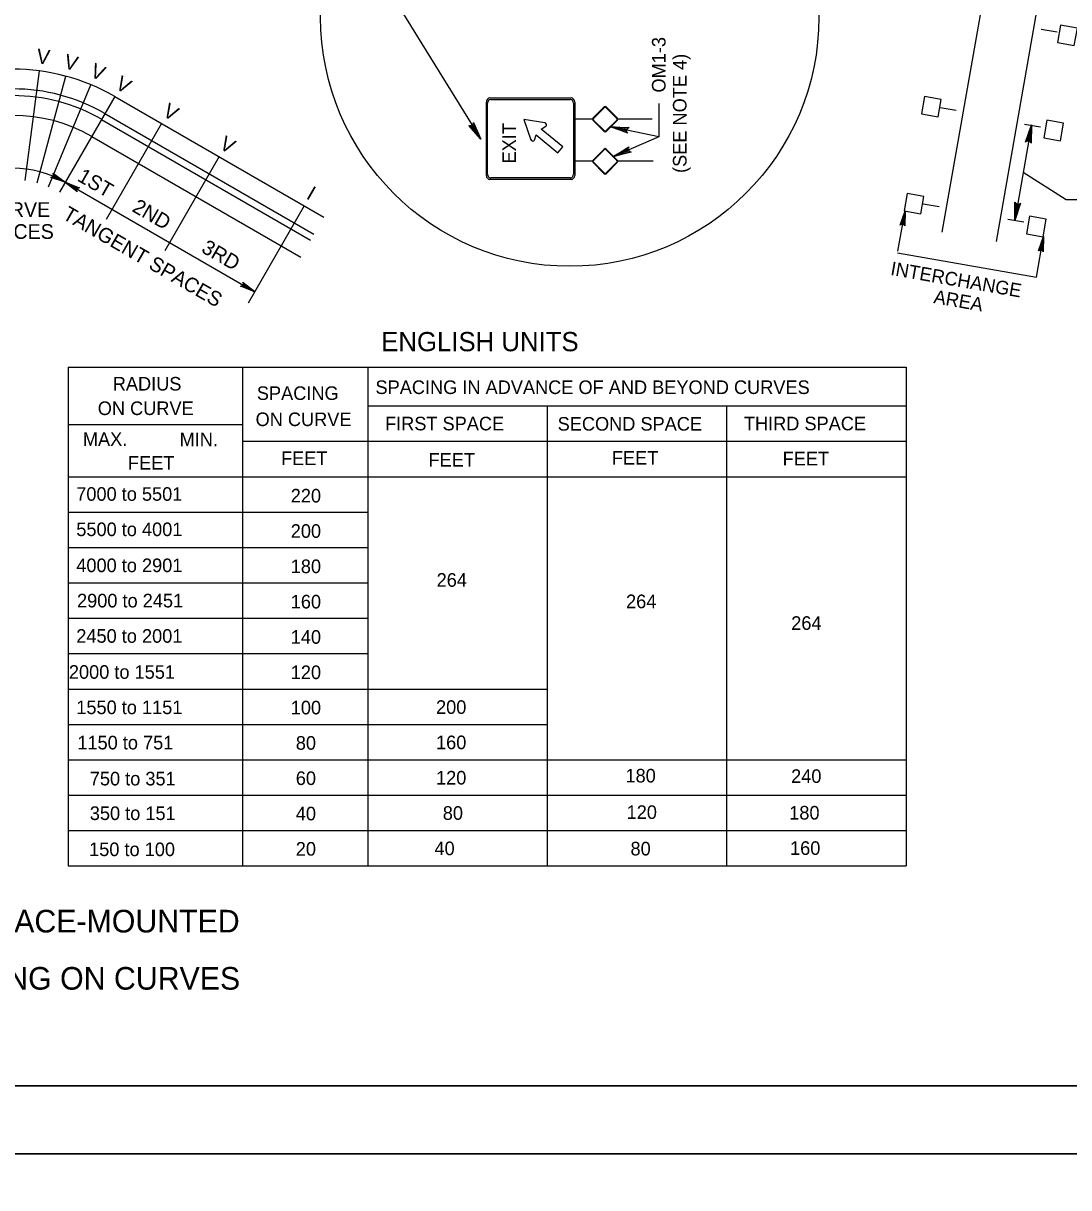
# Model space of a CAD drawing. Extents: x 640253 to 641999, y 298458 to 299646.
# Drawn here: x 641345.5 to 641576.3, y 299044.1 to 299301.1 of the extents above; entities that cross this region are included whole.
import ezdxf

# ---------------------------------------------------------------- set-up
doc = ezdxf.new("R2010")
doc.units = 0
for name, color, linetype in [('1', 7, 'Continuous'), ('2', 7, 'Continuous'), ('PLT-BNDY', 7, 'Continuous')]:
    doc.layers.add(name, color=color, linetype=linetype)

msp = doc.modelspace()

# ---------------------------------------------------------------- linework, layer by layer
at = {"layer": '1'}
for p, q in [((641447.76, 299267.56), (641447.76, 299283.76)), ((641448.05, 299267.83), (641448.05, 299283.49)), ((641448.54, 299284.66), (641466.48, 299284.66)), ((641448.77, 299284.33), (641466.25, 299284.33)), ((641466.97, 299283.49), (641466.97, 299267.83)), ((641467.26, 299283.76), (641467.26, 299267.56)), ((641471.26, 299280.16), (641473.79, 299282.69)), ((641471.39, 299280.15), (641473.81, 299282.56)), ((641474.16, 299282.56), (641476.58, 299280.15)), ((641474.18, 299282.69), (641476.71, 299280.16)), ((641471.18, 299279.96), (641466.97, 299279.96)), ((641484.35, 299279.96), (641476.79, 299279.96)), ((641460.69, 299279.14), (641456.07, 299279.87)), ((641456.07, 299279.87), (641457.61, 299275.45)), ((641459.89, 299277.79), (641460.91, 299278.41)), ((641464.62, 299273.86), (641459.89, 299277.79)), ((641473.79, 299277.24), (641471.26, 299279.77)), ((641473.81, 299277.37), (641471.39, 299279.79)), ((641476.58, 299279.79), (641474.16, 299277.37)), ((641476.71, 299279.77), (641474.18, 299277.24)), ((641458.38, 299275.37), (641458.79, 299276.49)), ((641458.79, 299276.49), (641463.53, 299272.55)), ((641463.53, 299272.55), (641464.62, 299273.86)), ((641471.26, 299270.85), (641473.79, 299273.39)), ((641471.39, 299270.84), (641473.81, 299273.26)), ((641474.16, 299273.26), (641476.58, 299270.84)), ((641474.18, 299273.39), (641476.71, 299270.85)), ((641471.18, 299270.7), (641466.97, 299270.7)), ((641473.79, 299267.93), (641471.26, 299270.47)), ((641473.81, 299268.06), (641471.39, 299270.48)), ((641476.58, 299270.48), (641474.16, 299268.06)), ((641476.71, 299270.47), (641474.18, 299267.93)), ((641484.56, 299270.7), (641476.79, 299270.7)), ((641466.48, 299266.66), (641448.54, 299266.66)), ((641466.25, 299267), (641448.77, 299267)), ((641920.31, 299066.63), (641134.31, 299066.63)), ((641134.31, 299066.63), (641720.31, 299066.63))]:
    msp.add_line(p, q, dxfattribs=at)
for centre, radius, start, end in [((641473.99, 299282.5), 0.275, 45, 135), ((641473.99, 299282.38), 0.252, 45, 135), ((641471.46, 299279.97), 0.275, 135, 225), ((641471.57, 299279.97), 0.252, 135, 225), ((641476.4, 299279.97), 0.252, 315, 45), ((641476.52, 299279.97), 0.275, 315, 45), ((641473.99, 299277.44), 0.275, 225, 315), ((641473.99, 299277.55), 0.252, 225, 315), ((641473.99, 299273.19), 0.275, 45, 135), ((641473.99, 299273.08), 0.252, 45, 135), ((641471.46, 299270.66), 0.275, 135, 225), ((641471.57, 299270.66), 0.252, 135, 225), ((641476.4, 299270.66), 0.252, 315, 45), ((641476.52, 299270.66), 0.275, 315, 45), ((641473.99, 299268.13), 0.275, 225, 315), ((641473.99, 299268.24), 0.252, 225, 315)]:
    msp.add_arc(centre, radius, start, end, dxfattribs=at)
for centre, major_axis, start_param, end_param in [((641448.54, 299283.76), (0, -0.9), 3.141593, 4.712389), ((641448.77, 299283.49), (0, -0.833), 3.141593, 4.712389), ((641466.25, 299283.49), (0, 0.833), 4.712389, 6.283185), ((641466.48, 299283.76), (0, 0.9), 4.712389, 6.283185), ((641460.66, 299278.75), (0.336, -0.279), 6.014589, 8.386103), ((641457.99, 299275.56), (-0.339, 0.282), 1.019875, 3.40872), ((641448.54, 299267.56), (0, -0.9), 4.712389, 6.283185), ((641448.77, 299267.83), (0, -0.833), 4.712389, 6.283185), ((641466.25, 299267.83), (0, 0.833), 3.141593, 4.712389), ((641466.48, 299267.56), (0, 0.9), 3.141593, 4.712389)]:
    msp.add_ellipse(centre, major_axis=major_axis, ratio=0.866667, start_param=start_param, end_param=end_param, dxfattribs=at)
at = {"layer": '2'}
for p, q in [((641548.4, 299255.06), (641564.23, 299345.46)), ((641560.38, 299252.96), (641575.95, 299342.02)), ((641421.94, 299315.4), (641446.55, 299275.57)), ((641570.22, 299299.84), (641570.22, 299299.84)), ((641570.22, 299299.84), (641573.75, 299299.22)), ((641345.98, 299266.45), (641349.15, 299290.63)), ((641348.59, 299265.92), (641354.9, 299289.48)), ((641351.14, 299265.06), (641360.47, 299287.59)), ((641365.73, 299284.99), (641353.56, 299263.87)), ((641365.73, 299284.99), (641411.88, 299258.34)), ((641485.84, 299283.45), (641485.84, 299276.05)), ((641363.56, 299281.22), (641409.71, 299254.58)), ((641551.46, 299281.88), (641547.94, 299282.5)), ((641551.46, 299281.88), (641551.46, 299281.88)), ((641362.81, 299279.93), (641408.96, 299253.29)), ((641376.07, 299279.03), (641363.84, 299257.8)), ((641485.84, 299276.05), (641475.26, 299278.32)), ((641568.09, 299278.74), (641564.39, 299257.61)), ((641566.56, 299278.89), (641566.56, 299278.89)), ((641566.56, 299278.89), (641570.08, 299278.27)), ((641360.64, 299276.17), (641406.79, 299249.53)), ((641485.84, 299276.05), (641475.82, 299271.75)), ((641388.76, 299271.71), (641376.78, 299250.93)), ((641575.72, 299262.19), (641566.24, 299268.18)), ((641354.81, 299266.05), (641396.62, 299241.9)), ((641407.56, 299260.88), (641395.18, 299239.4)), ((641538.63, 299250.84), (641540.19, 299259.77)), ((641547.73, 299260.6), (641544.2, 299261.22)), ((641547.73, 299260.6), (641547.73, 299260.6)), ((641562.9, 299257.94), (641562.9, 299257.94)), ((641562.9, 299257.94), (641566.42, 299257.32)), ((641560.38, 299252.96), (641560.38, 299252.96)), ((641569.2, 299245.13), (641570.76, 299254.06)), ((641538.53, 299250.5), (641569.2, 299245.13)), ((641355.44, 299225.24), (641355.44, 299115.14)), ((641355.44, 299225.24), (641540.45, 299225.24)), ((641393.93, 299225.24), (641393.93, 299115.14)), ((641421.58, 299225.24), (641421.58, 299115.14)), ((641540.45, 299225.24), (641540.45, 299115.14)), ((641421.58, 299216.68), (641540.45, 299216.68)), ((641426.39, 299216.68), (641426.39, 299216.68)), ((641461.18, 299216.68), (641461.18, 299115.14)), ((641461.73, 299216.68), (641461.73, 299216.68)), ((641497.07, 299216.68), (641497.07, 299216.68)), ((641500.78, 299216.68), (641500.78, 299115.14)), ((641532.41, 299216.68), (641532.41, 299216.68)), ((641355.44, 299212.58), (641394, 299212.58)), ((641393.93, 299208.87), (641540.45, 299208.87)), ((641355.44, 299201.06), (641540.45, 299201.06)), ((641355.44, 299193.25), (641421.58, 299193.25)), ((641355.44, 299185.44), (641421.58, 299185.44)), ((641355.44, 299177.63), (641421.58, 299177.63)), ((641355.44, 299169.82), (641421.58, 299169.82)), ((641355.44, 299162.01), (641421.58, 299162.01)), ((641355.44, 299154.2), (641461.18, 299154.2)), ((641355.44, 299146.38), (641461.18, 299146.38)), ((641355.44, 299138.57), (641540.45, 299138.57)), ((641355.44, 299130.76), (641540.45, 299130.76)), ((641355.44, 299122.95), (641540.45, 299122.95)), ((641355.44, 299115.14), (641540.45, 299115.14))]:
    msp.add_line(p, q, dxfattribs=at)
for points in [[(641577.55, 299296.22), (641578.22, 299300.06), (641574.53, 299300.71), (641573.85, 299296.87)], [(641547.5, 299280.48), (641548.17, 299284.32), (641544.48, 299284.97), (641543.81, 299281.13)], [(641574.52, 299275.23), (641575.19, 299279.07), (641571.5, 299279.72), (641570.83, 299275.88)], [(641543.67, 299259.09), (641544.34, 299262.93), (641540.65, 299263.57), (641539.98, 299259.73)], [(641570.69, 299254.04), (641571.36, 299257.88), (641567.67, 299258.53), (641567, 299254.69)]]:
    msp.add_lwpolyline(points, close=True, dxfattribs=at)
for points in [[(641444.9, 299279), (641444.75, 299278.74), (641446.55, 299275.57), (641444.9, 299279), (641444.93, 299279.26), (641446.55, 299275.57), (641444.43, 299278.53), (641444.13, 299278.49), (641446.55, 299275.57), (641443.87, 299278.57), (641444.13, 299278.49)], [(641478.86, 299277.06), (641478.78, 299277.36), (641475.26, 299278.32), (641478.86, 299277.06), (641479.01, 299276.86), (641475.26, 299278.32), (641478.86, 299277.74), (641479.04, 299277.97), (641475.26, 299278.32), (641479.28, 299278.1), (641479.04, 299277.97)], [(641566.97, 299275.09), (641567.26, 299275.18), (641568.09, 299278.74), (641566.97, 299275.09), (641566.77, 299274.93), (641568.09, 299278.74), (641567.64, 299275.12), (641567.88, 299274.94), (641568.09, 299278.74), (641568.03, 299274.71), (641567.88, 299274.94)], [(641479.49, 299272.79), (641479.25, 299272.99), (641475.82, 299271.75), (641479.49, 299272.79), (641479.73, 299272.72), (641475.82, 299271.75), (641479.1, 299273.34), (641479.11, 299273.64), (641475.82, 299271.75), (641479.23, 299273.89), (641479.11, 299273.64)], [(641352.17, 299267.84), (641352.17, 299267.58), (641354.81, 299266.05), (641352.17, 299267.84), (641352.1, 299268.03), (641354.81, 299266.05), (641352.03, 299267.28), (641351.84, 299267.14), (641354.81, 299266.05), (641351.62, 299267.07), (641351.84, 299267.14)], [(641357.34, 299264.12), (641357.36, 299264.38), (641354.81, 299266.05), (641357.34, 299264.12), (641357.41, 299263.93), (641354.81, 299266.05), (641357.52, 299264.66), (641357.73, 299264.8), (641354.81, 299266.05), (641357.95, 299264.85), (641357.73, 299264.8)], [(641608.47, 299262.19), (641575.72, 299262.19)], [(641539.26, 299256.73), (641539.5, 299256.8), (641540.19, 299259.77), (641539.26, 299256.73), (641539.1, 299256.59), (641540.19, 299259.77), (641539.81, 299256.75), (641540.02, 299256.61), (641540.19, 299259.77), (641540.14, 299256.42), (641540.02, 299256.61)], [(641565.51, 299261.26), (641565.22, 299261.17), (641564.39, 299257.61), (641565.51, 299261.26), (641565.71, 299261.42), (641564.39, 299257.61), (641564.84, 299261.23), (641564.6, 299261.41), (641564.39, 299257.61), (641564.45, 299261.64), (641564.6, 299261.41)], [(641569.82, 299251.02), (641570.06, 299251.09), (641570.76, 299254.06), (641569.82, 299251.02), (641569.67, 299250.88), (641570.76, 299254.06), (641570.38, 299251.03), (641570.59, 299250.9), (641570.76, 299254.06), (641570.71, 299250.71), (641570.59, 299250.9)], [(641394.09, 299243.83), (641394.07, 299243.57), (641396.62, 299241.9), (641394.09, 299243.83), (641394.02, 299244.02), (641396.62, 299241.9), (641393.92, 299243.29), (641393.71, 299243.15), (641396.62, 299241.9), (641393.48, 299243.1), (641393.71, 299243.15)]]:
    msp.add_lwpolyline(points, dxfattribs=at)
msp.add_circle((641466.18, 299302.5), 55, dxfattribs=at)
for radius in [44.9, 40.55, 39.07, 34.71, 23.03]:
    msp.add_arc((641343.29, 299246.1), radius, 60.0122, 120.0089, dxfattribs=at)
at = {"layer": 'PLT-BNDY'}
for points in [[(641094.31, 299645.63), (641935.31, 299645.63), (641935.31, 299051.63), (641094.31, 299051.63)], [(641094.31, 299051.63), (641935.31, 299051.63), (641935.31, 298457.63), (641094.31, 298457.63)]]:
    msp.add_lwpolyline(points, close=True, dxfattribs=at)

# ---------------------------------------------------------------- texts
at = {"layer": '1'}
msp.add_text('EXIT', height=3, rotation=90, dxfattribs=at).set_placement((641454.29, 299270.2))
at = {"layer": '2'}
for s, height, rotation, p in [('V', 3.25, 352.4868, (641348.3, 299292.35)), ('OM1-3', 3, 90, (641487.32, 299285.85)), ('V', 3.25, 344.9847, (641354.29, 299291.29)), ('(SEE NOTE 4)', 3, 90, (641491.95, 299268.1)), ('V', 3.25, 337.4827, (641360.09, 299289.46)), ('V', 3.25, 330.0028, (641365.62, 299286.91)), ('V', 3.25, 330.0028, (641365.62, 299286.91)), ('V', 3.25, 330.0028, (641376.07, 299280.87)), ('V', 3.25, 330.0028, (641388.59, 299273.65)), ('1ST', 3.246, 329.9971, (641357.26, 299266.5)), ('I', 3.25, 330.0028, (641407.8, 299262.56)), ('2ND', 3.246, 329.9971, (641369.35, 299259.75)), ('TANGENT SPACES', 3.2458, 330, (641353.97, 299258.12)), ('3RD', 3.246, 329.9971, (641384.63, 299250.76)), ('INTERCHANGE', 3, 350.0808, (641536.84, 299245.63)), ('AREA', 3, 350.0808, (641546.35, 299239.4))]:
    msp.add_text(s, height=height, rotation=rotation, dxfattribs=at).set_placement(p)
for s, height, p in [('CURVE', 3.246, (641336.29, 299258.41)), ('SPACES', 3.246, (641334.67, 299253.55)), ('ENGLISH UNITS', 4.25, (641424.55, 299228.75)), ('RADIUS', 3, (641365.29, 299220.08)), ('SPACING', 3, (641397.1, 299218)), ('SPACING IN ADVANCE OF AND BEYOND CURVES', 3, (641423.29, 299219.31)), ('ON CURVE', 3, (641361.98, 299214.67)), ('ON CURVE', 3, (641396.82, 299212.23)), ('FIRST SPACE', 3, (641425.39, 299211.29)), ('SECOND SPACE', 3, (641463.5, 299211.23)), ('THIRD SPACE', 3, (641504.61, 299211.3)), ('MAX.', 3, (641358.69, 299207.86)), ('MIN.', 3, (641380.05, 299207.79)), ('FEET', 3, (641368.65, 299202.62)), ('FEET', 3, (641402.44, 299203.64)), ('FEET', 3, (641435, 299203.28)), ('FEET', 3, (641475.46, 299203.72)), ('FEET', 3, (641513.17, 299203.55)), ('7000 to 5501', 3, (641357.23, 299195.75)), ('220', 3, (641404.58, 299195.37)), ('5500 to 4001', 3, (641357.24, 299187.95)), ('200', 3, (641404.58, 299187.57)), ('4000 to 2901', 3, (641357.24, 299180)), ('180', 3, (641404.58, 299179.78)), ('264', 3, (641436.78, 299176.77)), ('2900 to 2451', 3, (641357.4, 299172.21)), ('160', 3, (641404.58, 299171.98)), ('264', 3, (641478.6, 299172.04)), ('264', 3, (641515.06, 299167.26)), ('2450 to 2001', 3, (641357.24, 299164.41)), ('140', 3, (641404.58, 299164.19)), (' 2000 to 1551', 3, (641354.49, 299156.46)), ('120', 3, (641404.58, 299156.39)), ('1550 to 1151', 3, (641357.24, 299148.66)), ('100', 3, (641404.58, 299148.6)), ('200', 3, (641436.65, 299148.71)), ('1150 to 751', 3, (641357.47, 299140.87)), (' 80', 3, (641404.58, 299140.8)), ('160', 3, (641436.65, 299140.92)), (' 60', 3, (641404.58, 299133.01)), ('120', 3, (641436.65, 299133.12)), ('180', 3, (641478.47, 299133.57)), ('240', 3, (641515.04, 299133.47)), ('750 to 351', 3, (641360.22, 299132.92)), ('350 to 151', 3, (641360.22, 299125.28)), ('80', 3, (641438.14, 299125.33)), ('120', 3, (641478.72, 299125.52)), ('180', 3, (641514.62, 299125.39)), (' 40', 3, (641404.58, 299125.21)), ('160', 3, (641514.8, 299117.59)), ('150 to 100', 3, (641360.07, 299117.32)), (' 20', 3, (641404.58, 299117.42)), (' 40', 3, (641435.19, 299117.53)), (' 80', 3, (641478.47, 299117.47)), ('GROUND/SURFACE-MOUNTED', 5, (641293.76, 299100.46)), ('DELINEATOR SPACING ON CURVES', 5, (641277.13, 299087.84))]:
    msp.add_text(s, height=height, dxfattribs=at).set_placement(p)

doc.saveas('drawing.dxf')
